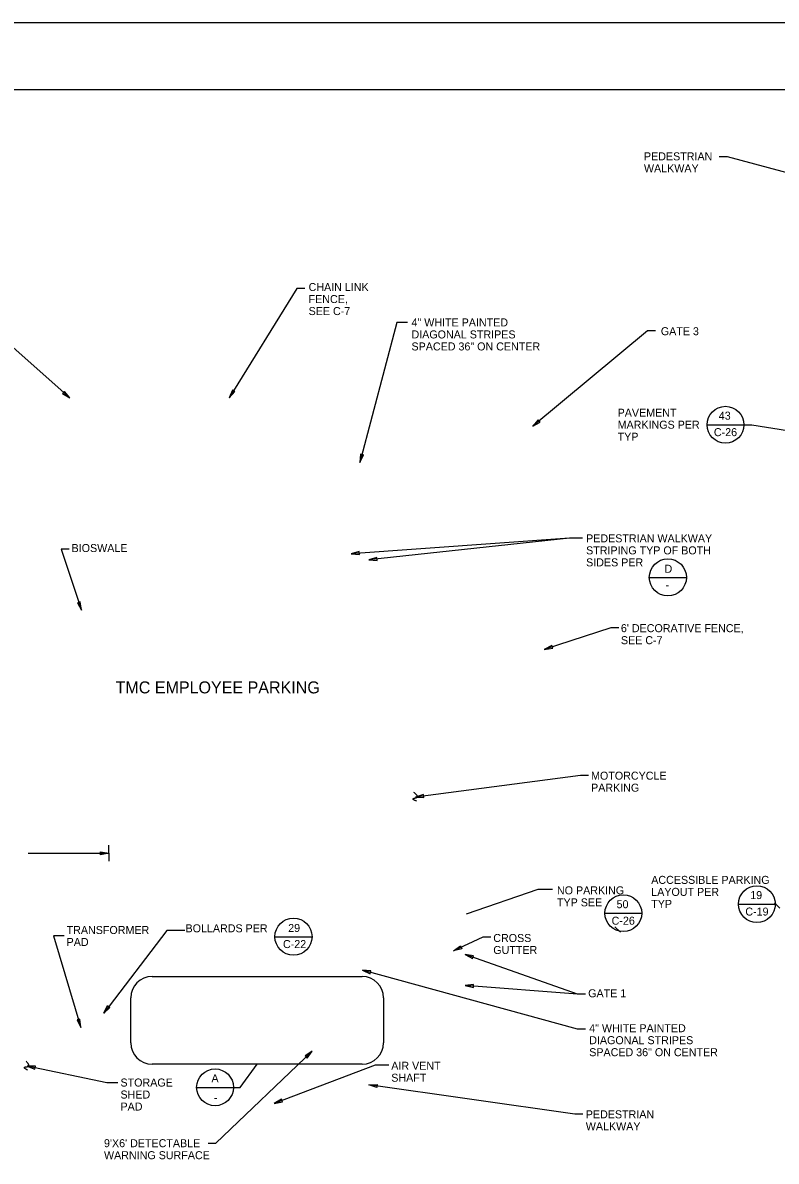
# Model space of a CAD drawing. Extents: x 0 to 4.19, y 0 to 2.5.
# Drawn here: x 1.504 to 2.446, y 1.078 to 2.5 of the extents above; entities that cross this region are included whole.
import ezdxf

# ---------------------------------------------------------------- set-up
doc = ezdxf.new("R2010")
doc.units = 0
for name, color, linetype in [('C-MARK', 7, 'Continuous'), ('C-TEXT', 7, 'Continuous'), ('C-TEXT-TITL', 7, 'Continuous'), ('G-TTLB-OTLN', 7, 'Continuous'), ('G-TTLB-VIEW', 7, 'Continuous'), ('Level 11', 7, 'Continuous')]:
    doc.layers.add(name, color=color, linetype=linetype)

msp = doc.modelspace()

# ---------------------------------------------------------------- linework, layer by layer
at = {"layer": 'C-MARK'}
for p, q in [((2.3591, 1.9978), (2.4051, 1.9978)), ((1.6113, 1.4624), (1.6113, 1.4724)), ((1.5107, 1.4624), (1.6113, 1.4624)), ((1.6113, 1.4624), (1.6113, 1.4524)), ((2.1476, 1.4171), (2.0579, 1.3862)), ((2.1661, 1.4171), (2.1476, 1.4171)), ((2.3984, 1.3988), (2.4444, 1.3988)), ((2.2314, 1.3874), (2.2774, 1.3874)), ((1.6655, 1.3083), (1.9281, 1.3083)), ((1.6388, 1.2256), (1.6388, 1.2817)), ((1.9548, 1.2817), (1.9548, 1.2256)), ((1.9281, 1.1989), (1.6655, 1.1989)), ((1.7756, 1.1699), (1.797, 1.1989)), ((1.7212, 1.1699), (1.7672, 1.1699)), ((1.7672, 1.1699), (1.7756, 1.1699))]:
    msp.add_line(p, q, dxfattribs=at)
for points in [[(2.3741, 2.3331), (2.3841, 2.3331), (2.527, 2.2947)], [(1.8564, 2.1678), (1.8464, 2.1678), (1.7619, 2.0313)], [(1.4069, 2.1604), (1.4169, 2.1604), (1.5626, 2.0313)], [(1.9846, 2.1254), (1.9714, 2.1254), (1.9251, 1.9504)], [(2.2947, 2.1149), (2.2847, 2.1149), (2.1412, 1.9959)], [(2.4051, 1.9978), (2.4151, 1.9978), (2.5829, 1.9711)], [(2.187, 1.856), (1.9141, 1.8366)], [(2.2034, 1.856), (2.187, 1.856), (1.9363, 1.829)], [(1.5618, 1.8424), (1.5518, 1.8424), (1.5772, 1.766)], [(2.2488, 1.744), (2.2388, 1.744), (2.1557, 1.717)], [(2.2108, 1.5594), (2.2008, 1.5594), (1.9947, 1.5324)], [(1.7066, 1.3659), (1.6841, 1.3659), (1.605, 1.2626)], [(1.5557, 1.3593), (1.5425, 1.3593), (1.5766, 1.2447)], [(2.0888, 1.3575), (2.0788, 1.3575), (2.0422, 1.3404)], [(2.2073, 1.2865), (2.1973, 1.2865), (2.0568, 1.336)], [(2.2073, 1.2427), (2.1973, 1.2427), (1.9283, 1.3161)], [(2.2073, 1.2865), (2.1973, 1.2865), (2.0568, 1.2973)], [(1.7355, 1.1001), (1.7452, 1.1001), (1.8654, 1.2151)], [(1.6227, 1.1757), (1.609, 1.1757), (1.5092, 1.1965)], [(1.9614, 1.1976), (1.9445, 1.1976), (1.8181, 1.1498)], [(2.2038, 1.1362), (2.1938, 1.1362), (1.9363, 1.1729)]]:
    msp.add_lwpolyline(points, dxfattribs=at)
for centre in [(2.3821, 1.9978), (2.2544, 1.3874), (2.4214, 1.3988), (1.7442, 1.1699)]:
    msp.add_circle(centre, 0.023, dxfattribs=at)
for centre, start, end in [((1.6655, 1.2817), 90, 180), ((1.9281, 1.2817), 360, 90), ((1.6655, 1.2256), 180, 270), ((1.9281, 1.2256), 270, 360)]:
    msp.add_arc(centre, 0.0267, start, end, dxfattribs=at)
for points in [[(1.9959, 1.5275), (1.9882, 1.5304), (2.0004, 1.5325), (1.9928, 1.5382)], [(1.5097, 1.1914), (1.5025, 1.1954), (1.5148, 1.1959), (1.508, 1.2025)]]:
    msp.add_open_spline(points, degree=2, dxfattribs=at)
at = {"layer": 'C-TEXT'}
for p, q in [((2.2869, 1.807), (2.3333, 1.807)), ((1.819, 1.3581), (1.8654, 1.3581))]:
    msp.add_line(p, q, dxfattribs=at)
for points in [[(1.5535, 2.0367), (1.5626, 2.0313), (1.556, 2.0395)], [(1.7658, 2.0411), (1.7619, 2.0313), (1.7689, 2.0392)], [(2.1481, 2.0039), (2.1412, 1.9959), (2.1504, 2.0011)], [(1.926, 1.9609), (1.9251, 1.9504), (1.9296, 1.96)], [(1.9243, 1.8392), (1.9141, 1.8366), (1.9246, 1.8355)], [(1.9465, 1.832), (1.9363, 1.829), (1.9469, 1.8283)], [(1.5722, 1.7753), (1.5772, 1.766), (1.5757, 1.7765)], [(2.165, 1.7221), (2.1557, 1.717), (2.1662, 1.7186)], [(2.0048, 1.5357), (1.9947, 1.5324), (2.0053, 1.5321)], [(1.6009, 1.4643), (1.6113, 1.4624), (1.6009, 1.4606)], [(2.0525, 1.3431), (2.0422, 1.3404), (2.0509, 1.3465)], [(2.0672, 1.3343), (2.0568, 1.336), (2.066, 1.3308)], [(1.9388, 1.3153), (1.9283, 1.3161), (1.9379, 1.3117)], [(2.0673, 1.2984), (2.0568, 1.2973), (2.067, 1.2947)], [(1.6128, 1.2698), (1.605, 1.2626), (1.6099, 1.272)], [(1.5718, 1.2541), (1.5766, 1.2447), (1.5753, 1.2552)], [(1.8593, 1.2065), (1.8654, 1.2151), (1.8567, 1.2091)], [(1.5198, 1.1963), (1.5092, 1.1965), (1.519, 1.1927)], [(1.9464, 1.1696), (1.9363, 1.1729), (1.9469, 1.1733)], [(1.8272, 1.1552), (1.8181, 1.1498), (1.8285, 1.1518)]]:
    msp.add_lwpolyline(points, close=True, dxfattribs=at)
for centre in [(2.3101, 1.807), (1.8422, 1.3581)]:
    msp.add_circle(centre, 0.0232, dxfattribs=at)
at = {"layer": 'G-TTLB-OTLN'}
msp.add_lwpolyline([(0, 0), (3.5, 0), (3.5, 2.5), (0, 2.5)], close=True, dxfattribs=at)
msp.add_lwpolyline([(0, 0), (3.5, 0), (3.5, 2.5), (0, 2.5)], close=True, dxfattribs=at)
at = {"layer": 'G-TTLB-VIEW'}
msp.add_lwpolyline([(0.1667, 2.4167), (3.0729, 2.4167), (3.0729, 0.0833), (0.1667, 0.0833)], close=True, dxfattribs=at)
at = {"layer": 'Level 11'}
for p, q in [((2.4502, 1.3937), (2.4433, 1.4005)), ((2.2507, 1.3636), (2.2438, 1.3704))]:
    msp.add_line(p, q, dxfattribs=at)

# ---------------------------------------------------------------- texts
at = {"layer": 'C-TEXT'}
for s, p in [('PEDESTRIAN', (2.2802, 2.3281)), ('WALKWAY', (2.2802, 2.3131)), ('CHAIN LINK', (1.8611, 2.1648)), ('FENCE,', (1.8611, 2.1498)), ('SEE C-7', (1.8611, 2.1348)), ('4" WHITE PAINTED', (1.9897, 2.1206)), ('GATE 3', (2.3013, 2.1096)), ('DIAGONAL STRIPES', (1.9897, 2.1056)), ('SPACED 36" ON CENTER', (1.9897, 2.0906)), ('PAVEMENT', (2.2473, 2.0078)), ('43', (2.3737, 2.0041)), ('MARKINGS PER', (2.2473, 1.9928)), ('C-26', (2.3676, 1.9835)), ('TYP', (2.2473, 1.9778)), ('PEDESTRIAN WALKWAY', (2.2079, 1.8508)), ('STRIPING TYP OF BOTH', (2.2079, 1.8358)), ('SIDES PER', (2.2079, 1.8208)), ('D', (2.3059, 1.8128)), ('-', (2.3073, 1.7927)), ("6' DECORATIVE FENCE,", (2.2514, 1.7386)), ('SEE C-7', (2.2514, 1.7236)), ('ACCESSIBLE PARKING', (2.2893, 1.4241)), ('NO PARKING', (2.1715, 1.411)), ('LAYOUT PER', (2.2893, 1.4091)), ('19', (2.413, 1.4051)), ('TYP SEE', (2.1715, 1.396)), ('50', (2.246, 1.3937)), ('TYP', (2.2893, 1.3941)), ('C-19', (2.4069, 1.3845)), ('C-26', (2.2398, 1.3731)), ('29', (1.8356, 1.364)), ('C-22', (1.8291, 1.3439)), ('GATE 1', (2.2105, 1.2824)), ('4" WHITE PAINTED', (2.2118, 1.2388)), ('DIAGONAL STRIPES', (2.2118, 1.2238)), ('SPACED 36" ON CENTER', (2.2118, 1.2088)), ('AIR VENT', (1.9644, 1.1919)), ('A', (1.7397, 1.1762)), ('SHAFT', (1.9644, 1.1769)), ('-', (1.7429, 1.1522)), ('PEDESTRIAN', (2.2075, 1.1312)), ('WALKWAY', (2.2075, 1.1162)), ("9'X6' DETECTABLE", (1.6054, 1.0951)), ('WARNING SURFACE', (1.6054, 1.0801))]:
    msp.add_text(s, height=0.01, dxfattribs=at).set_placement(p)
for s, p in [('BIOSWALE', (1.5649, 1.8387)), ('MOTORCYCLE', (2.2141, 1.5543)), ('PARKING', (2.2141, 1.5393)), ('TRANSFORMER', (1.5587, 1.3615)), ('BOLLARDS PER', (1.7073, 1.3636)), ('PAD', (1.5587, 1.3465)), ('CROSS', (2.0919, 1.3515)), ('GUTTER', (2.0919, 1.3365)), ('STORAGE', (1.626, 1.1709)), ('SHED', (1.626, 1.1559)), ('PAD', (1.626, 1.1409))]:
    msp.add_text(s, height=0.01, rotation=360, dxfattribs=at).set_placement(p)
at = {"layer": 'C-TEXT-TITL'}
msp.add_text('TMC EMPLOYEE PARKING', height=0.015, dxfattribs=at).set_placement((1.6199, 1.6621))

doc.saveas('drawing.dxf')
